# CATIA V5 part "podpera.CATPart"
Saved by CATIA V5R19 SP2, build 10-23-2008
Part number: podpera
Material "Steel": density 7860 kg/m3, Young's modulus 2e+11 Pa, Poisson ratio 0.266, thermal expansion 1.17e-05 1/K
Bounding box of the stored display mesh (mm): x -10 to 10, y -20 to 20, z 0 to 21
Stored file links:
  C:\Documents and Settings\JiriPesek\Dokumenty\catia\podpera.CATPart
  D:\Program Files\Dassault Systemes\B19\intel_a\startup\materials\Catalog.CATMaterial
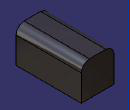
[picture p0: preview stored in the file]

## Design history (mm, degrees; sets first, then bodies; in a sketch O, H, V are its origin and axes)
AxisSystem1: origin (0, 0, 0), X (1, 0, 0), Y (0, 1, 0), Z (0, 0, 1)
Body1 (main body)
  Sketch1 on XY plane of AxisSystem1, origin (0, 0, 0), H (1, 0, 0), V (0, 1, 0)
    line L1 (10, 20) -> (10, -20)
    line L2 (10, -20) -> (-10, -20)
    line L3 (-10, -20) -> (-10, 20)
    line L4 (-10, 20) -> (10, 20)
    distance L2 L4 = 40
    distance L1 L3 = 20
    vertical: L1 V, L3 V
    horizontal: L2 H, L4 H
    equidistance: L1 L3 O, L2 L4 O
  Pad1: profile Sketch1, direction (0, 0, 1), length 21
  Fillet1: radius 5, on edge [face of Pad1 from Sketch1.L1 | end face of Pad1]; edge [face of Pad1 from Sketch1.L3 | end face of Pad1]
